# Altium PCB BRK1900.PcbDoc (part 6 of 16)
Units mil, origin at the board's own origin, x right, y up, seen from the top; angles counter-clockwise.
Board outline 8858.27 x 5905.51 mil, 10 copper layers (L1-TOP, L2-GND, L3-PWR, L4-GND, L5-PWR, L6-PWR, L7-GND, L8-SIG, L9-GND, L10-BOT), stack 48.824 mil thick; 456 components, 571 nets, 2296 pads, 2416 vias.
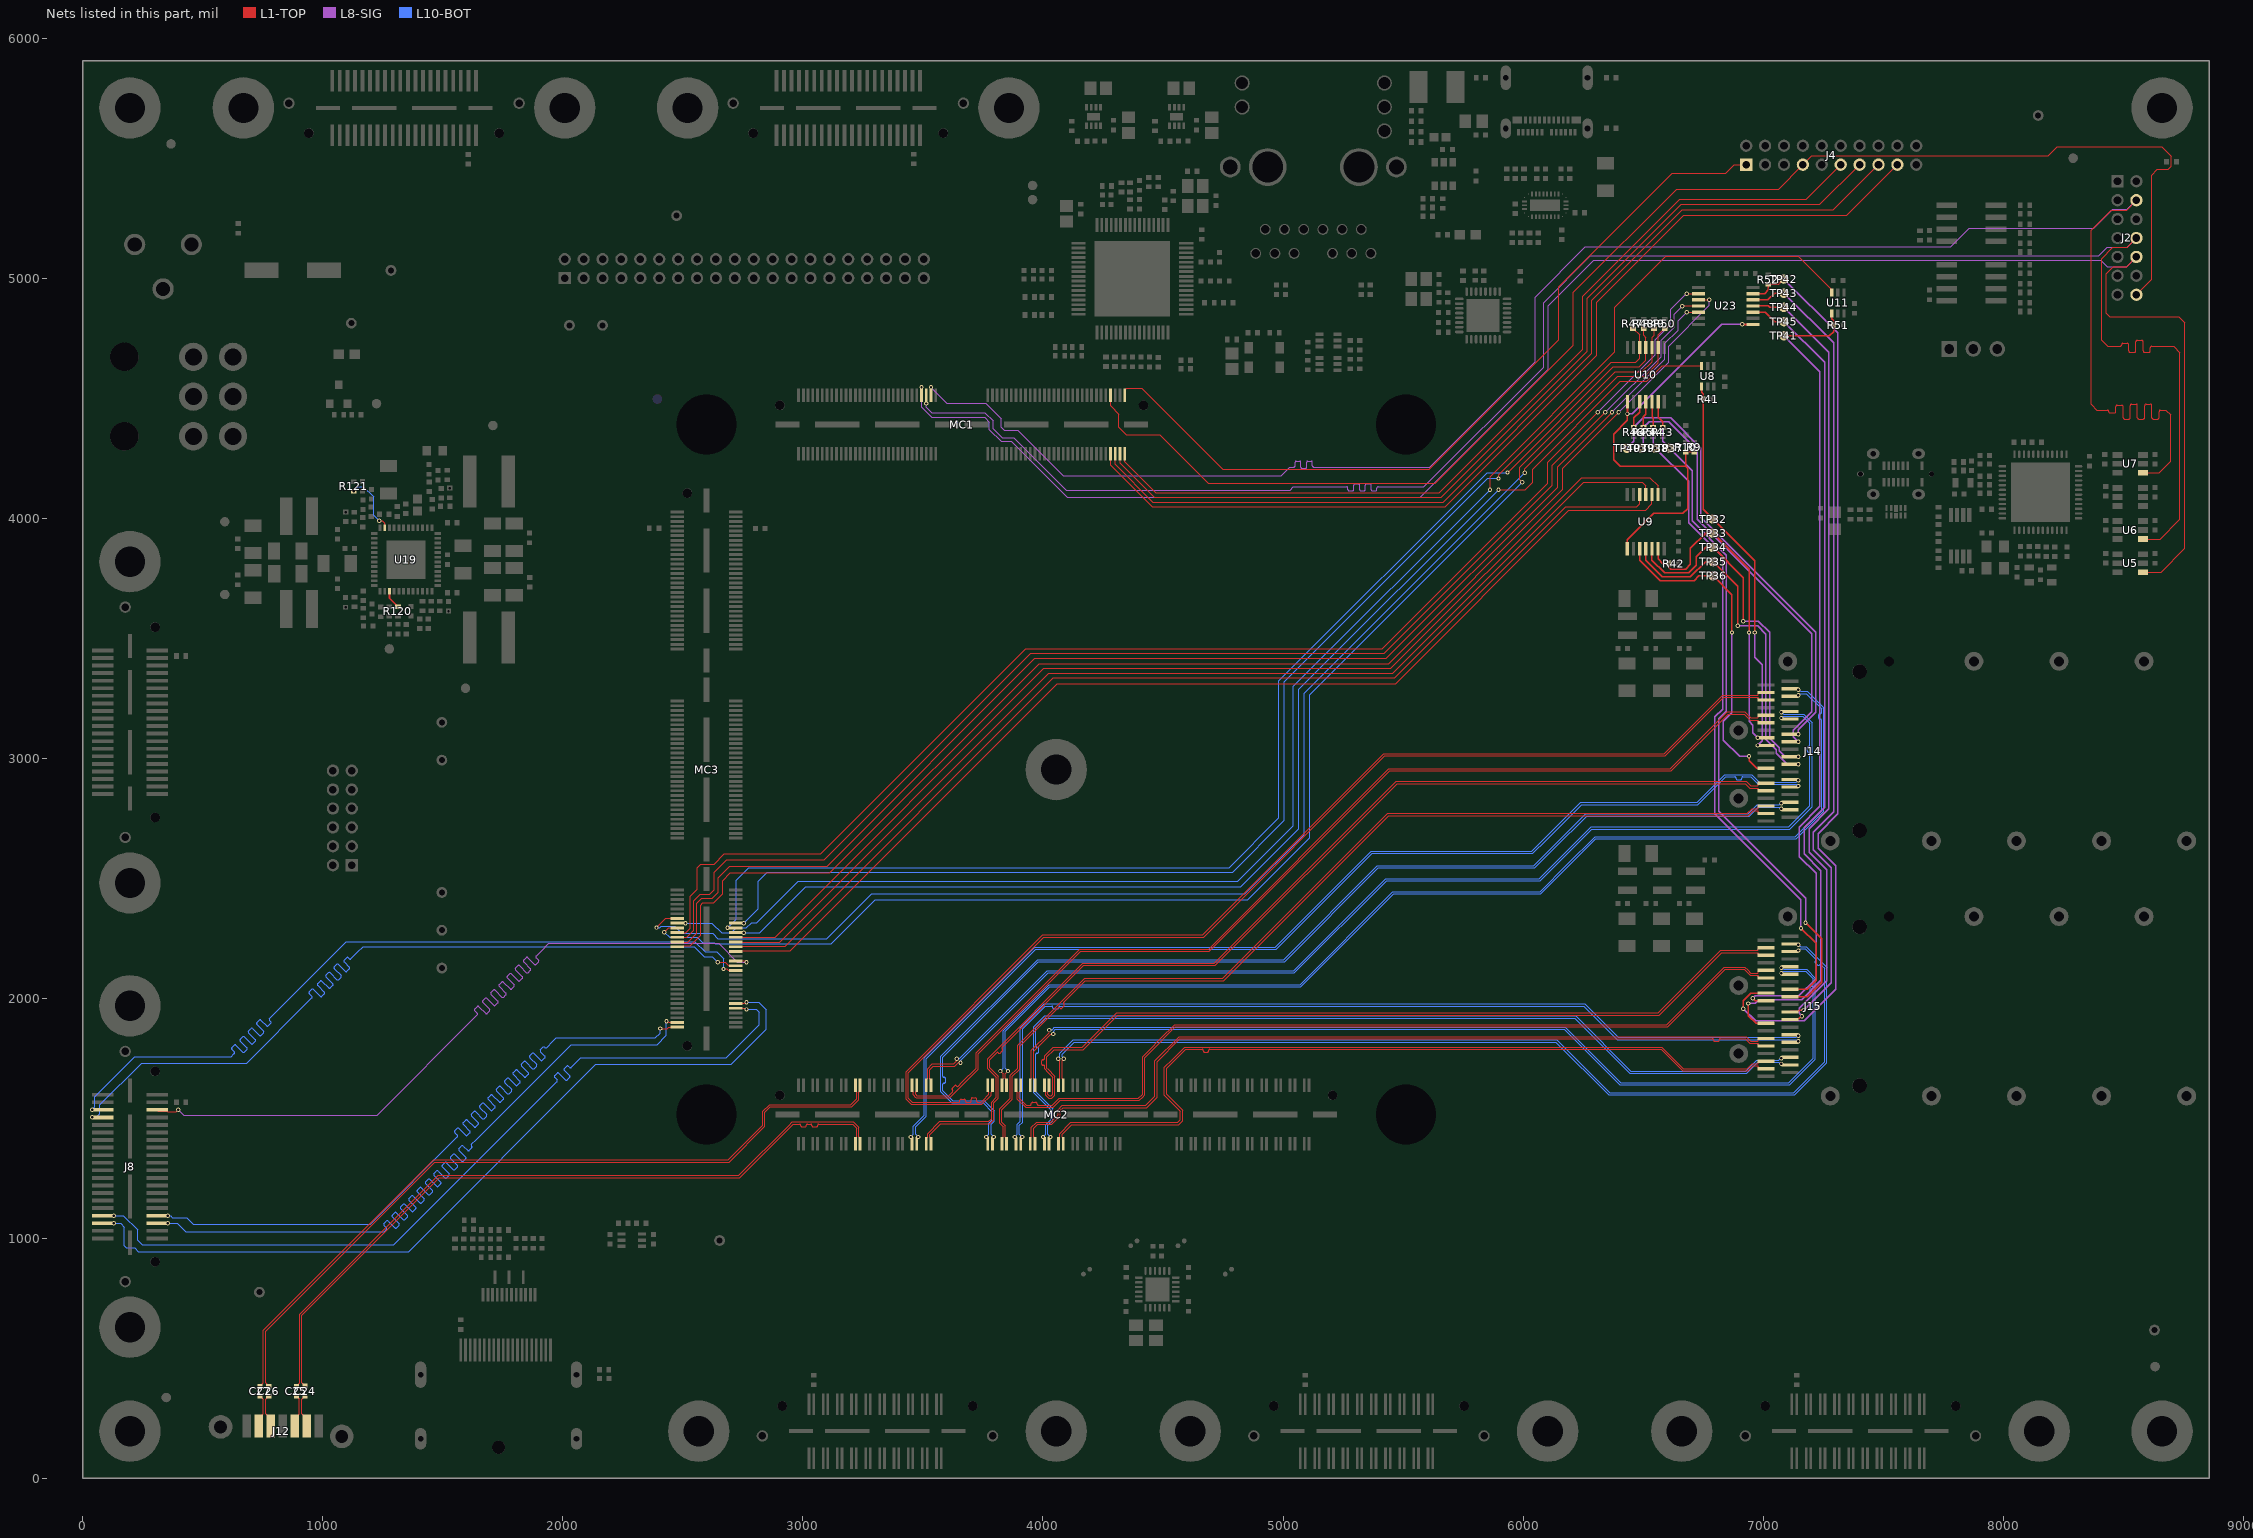
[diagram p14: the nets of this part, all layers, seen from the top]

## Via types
v1: diameter 18, hole 10, L1-TOP to L10-BOT, tented both sides, 2170 vias
v2: diameter 20, hole 10, L1-TOP to L10-BOT, tented both sides, 246 vias

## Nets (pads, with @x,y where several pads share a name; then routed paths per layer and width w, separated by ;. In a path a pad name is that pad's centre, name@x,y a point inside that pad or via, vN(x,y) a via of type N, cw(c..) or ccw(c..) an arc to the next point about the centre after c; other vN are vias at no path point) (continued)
PS_JTAG_TDI: J2.10 MC1.53 U5.4 | length 7725.6
  L1-TOP w4.96: J2.10@8554.76,5088.26 8513.74,5047.24 8458.82,5047.24 8429.13,5017.56 8429.13,4854.33 8444.02,4839.44 8730.86,4839.44 8755.91,4814.4 8755.91,3874.02 8657.1,3775.21 U5.4@8582.3,3775.21
  L8-SIG w4.05: v1(3494.09,4545.42) 3494.09,4462.26 3536.74,4419.62 3756.78,4419.62 3775.96,4400.44 3775.96,4369.22 3825.28,4319.9 3867.73,4319.9 4100.63,4087 5571.48,4087 6104.21,4619.73 6104.21,4884.72 6293.49,5074 8406.31,5074 8432.57,5047.74 8514.24,5047.74 J2.10@8554.76,5088.26
PS_JTAG_TDO: J2.8 MC1.55 U6.4 | length 7834.5
  L1-TOP w4.96: J2.8@8554.76,5167 8515.5,5127.74 8456.07,5127.74 8409.45,5081.12 8409.45,4740.55 8434.51,4715.49 8444.88,4715.49 8486.7,4715.49 ccw(c8486.7,4721.48) 8492.69,4721.48 8492.69,4722.4 cw(c8498.69,4722.4) 8498.69,4728.39 8516.66,4728.39 cw(c8516.66,4722.4) 8522.66,4722.4 8522.66,4696.48 ccw(c8528.65,4696.48) 8528.65,4690.49 8546.63,4690.49 ccw(c8546.63,4696.48) 8552.62,4696.48 8552.62,4734.49 cw(c8558.61,4734.49) 8558.61,4740.49 8576.59,4740.49 cw(c8576.59,4734.49) 8582.58,4734.49 8582.58,4696.48 ccw(c8588.58,4696.48) 8588.58,4690.49 8606.55,4690.49 ccw(c8606.55,4696.48) 8612.55,4696.48 8612.55,4709.49 cw(c8618.54,4709.49) 8618.54,4715.49 8621.02,4715.49 8710.1,4715.49 8736.22,4689.37 8736.22,3996.06 8653.16,3913.01 U6.4@8582.3,3913.01
  L8-SIG w4.05: v1(3513.78,4477.42) 3513.78,4462.93 3537.37,4439.34 3758.43,4439.34 3792.94,4404.82 3792.94,4372.36 3830.33,4334.97 3877.34,4334.97 4096.31,4116 5029.39,4116 5043.31,4129.92 5248.03,4129.92 5265.75,4129.92 cw(c5265.75,4125.11) 5270.56,4125.11 5270.56,4118.81 ccw(c5275.37,4118.81) 5275.37,4114 5289.8,4114 ccw(c5289.8,4118.81) 5294.61,4118.81 5294.61,4138.05 cw(c5299.42,4138.05) 5299.42,4142.86 5313.85,4142.86 cw(c5313.85,4138.05) 5318.66,4138.05 5318.66,4118.81 ccw(c5323.47,4118.81) 5323.47,4114 5337.9,4114 ccw(c5337.9,4118.81) 5342.71,4118.81 5342.71,4138.05 cw(c5347.52,4138.05) 5347.52,4142.86 5361.95,4142.86 cw(c5361.95,4138.05) 5366.76,4138.05 5366.76,4118.81 ccw(c5371.57,4118.81) 5371.57,4114 5386,4114 ccw(c5386,4118.81) 5390.81,4118.81 5390.81,4125.11 cw(c5395.62,4125.11) 5395.62,4129.92 5397.65,4129.92 5586.76,4129.92 6085.9,4629.06 6085.9,4897.58 6280.35,5092.03 8397.15,5092.03 8432.86,5127.74 8515.5,5127.74 J2.8@8554.76,5167
PS_JTAG_TMS: J2.4 MC1.57 U7.4 | length 7910.9
  L1-TOP w4.96: J2.4@8554.76,5324.48 8513.74,5283.46 8450.76,5283.46 8366.14,5198.84 8366.14,4474.52 8390.47,4450.19 8402.51,4450.19 8433.27,4450.19 cw(c8433.27,4444.2) 8439.26,4444.2 ccw(c8445.26,4444.2) 8445.26,4438.21 8463.24,4438.21 ccw(c8463.24,4444.2) 8469.23,4444.2 8469.23,4464.54 cw(c8475.22,4464.54) 8475.22,4470.53 8493.2,4470.53 cw(c8493.2,4464.54) 8499.19,4464.54 8499.19,4418.9 ccw(c8505.18,4418.9) 8505.18,4412.91 8523.16,4412.91 ccw(c8523.16,4418.9) 8529.15,4418.9 8529.15,4469.2 cw(c8535.15,4469.2) 8535.15,4475.19 8553.12,4475.19 cw(c8553.12,4469.2) 8559.12,4469.2 8559.12,4418.9 ccw(c8565.11,4418.9) 8565.11,4412.91 8583.09,4412.91 ccw(c8583.09,4418.9) 8589.08,4418.9 8589.08,4469.2 cw(c8595.07,4469.2) 8595.07,4475.19 8613.05,4475.19 cw(c8613.05,4469.2) 8619.04,4469.2 8619.04,4418.9 ccw(c8625.04,4418.9) 8625.04,4412.91 8643.01,4412.91 ccw(c8643.01,4418.9) 8649.01,4418.9 8649.01,4444.2 cw(c8655,4444.2) 8655,4450.19 8657.48,4450.19 8677.87,4450.19 8696.85,4431.21 8696.85,4236.22 8649.23,4188.6 U7.4@8582.3,4188.6
  L8-SIG w4.05: v1(3533.46,4545.42) 3599.93,4478.95 3761.2,4478.95 3826.77,4413.39 3826.77,4377.95 3839.57,4365.16 3895.34,4365.16 4083.5,4177 4991.96,4177 5027.56,4212.6 5043.31,4212.6 5045.33,4212.6 ccw(c5045.33,4217.41) 5050.14,4217.41 5050.14,4232.79 cw(c5054.95,4232.79) 5054.95,4237.6 5069.38,4237.6 cw(c5069.38,4232.79) 5074.19,4232.79 5074.19,4212.24 ccw(c5079,4212.24) 5079,4207.43 5093.43,4207.43 ccw(c5093.43,4212.24) 5098.24,4212.24 5098.24,4232.79 cw(c5103.05,4232.79) 5103.05,4237.6 5117.48,4237.6 cw(c5117.48,4232.79) 5122.29,4232.79 5122.29,4217.41 ccw(c5127.1,4217.41) 5127.1,4212.6 5173.23,4212.6 5610.49,4212.6 6050.21,4652.32 6050.21,4920.29 6259.52,5129.6 7781.6,5129.6 7859,5207 8377.28,5207 8456.02,5285.74 8516.02,5285.74 J2.4@8554.76,5324.48
PS_MODE0: J4.17 MC1.114 | length 4116.5
  L1-TOP w4.84: MC1.114@4281.5,4268.11 4281.5,4220.5 4454.76,4047.24 5674.95,4047.24 6306.48,4678.77 6306.48,4899.32 6669.16,5262 7348.61,5262 J4.17@7559.06,5472.44
PS_MODE1: J4.15 MC1.116 | length 3999.7
  L1-TOP w4.84: MC1.116@4301.18,4268.11 4301.18,4223.92 4458.17,4066.93 5666.8,4066.93 6286.8,4686.92 6286.8,4907.47 6663.32,5284 7291.87,5284 J4.15@7480.31,5472.44
PS_MODE2: J4.13 MC1.118 | length 3882.5
  L1-TOP w4.84: MC1.118@4320.87,4268.11 4320.87,4228.25 4462.5,4086.61 5658.65,4086.61 6267.11,4695.08 6267.11,4915.63 6658.48,5307 7236.13,5307 J4.13@7401.57,5472.44
PS_MODE3: J4.11 MC1.120 | length 3763.9
  L1-TOP w5: MC1.120@4340.55,4268.11 4340.55,4234.76 4469.02,4106.3 5650.49,4106.3 6247.43,4703.23 6247.43,4923.78 6652.64,5329 7179.39,5329 J4.11@7322.83,5472.44
PS_PROG_B: J4.1 MC1.119 | length 3406.8
  L1-TOP w5: MC1.119@4340.55,4511.42 4340.55,4532.55 4349,4541 4411.76,4541 4748.03,4204.72 5609.72,4204.72 6149,4744 6149,4964.55 6621.45,5437 6844,5437 6879.44,5472.44 J4.1@6929.13,5472.44
PS_SRST_B: J2.14 J4.7 MC1.113 | length 6019.7
  L1-TOP w4.84: MC1.113@4281.5,4511.42 4281.5,4467.22 4314.96,4433.76 4314.96,4377.95 4346.46,4346.46 4487.3,4346.46 4688.09,4145.67 5634.19,4145.67 6208.06,4719.54 6208.06,4940.09 6638.97,5371 7063.91,5371 J4.7@7165.35,5472.44 7202.91,5510 8187.17,5510 8224.41,5547.24 8661.19,5547.24 8700.31,5508.13 8700.31,5464.82 8688.24,5452.76 8641.73,5452.76 8618.11,5429.13 8618.11,4994.13 J2.14@8554.76,4930.78
QSFP1_INT_B: MC3.42 U8.3 | length 5339.4
  L1-TOP w5: v1(5897.64,4118.11) 6007.87,4118.11 6039.37,4149.61 6039.37,4204.72 6405.51,4570.87 6515.75,4570.87 6579.14,4634.26 U8.3@6743.31,4634.26
  L10-BOT w5: v1(2754.08,2273.62) 2820.62,2273.62 3011,2464 4824,2464 5065.96,2705.96 5065.96,3286.43 v1(5897.64,4118.11)
QSFP1_LP_MODE: MC3.36 U9.5 | length 4568.6
  L1-TOP w5: MC3.36@2720.08,2214.57 2722.51,2217 2925.66,2217 4043.31,3334.65 5464.57,3334.65 6177.17,4047.24 6472.44,4047.24 6485.42,4060.22 U9.5@6485.42,4098.98
QSFP1_MODPRS_B: MC3.40 U9.2 | length 4686
  L1-TOP w5: MC3.40@2720.08,2253.94 2883.86,2253.94 4003.94,3374.02 5448.82,3374.02 6244.09,4169.29 6528.38,4169.29 6562.19,4135.48 U9.2@6562.19,4098.98
QSFP1_MODSEL_B: MC3.38 U9.4 | length 4626.2
  L1-TOP w5: MC3.38@2720.08,2234.25 2903.54,2234.25 4023.62,3354.33 5456.69,3354.33 6251.97,4149.61 6496.06,4149.61 6511.01,4134.66 U9.4@6511.01,4098.98
QSFP1_RESET_B: MC3.34 U9.3 | length 4628.2
  L1-TOP w5: MC3.34@2720.08,2194.88 2743.88,2194.88 2748,2199 2947.03,2199 4059.06,3311.02 5468.5,3311.02 6190.89,4033.41 6510.27,4033.41 6536.6,4059.73 U9.3@6536.6,4098.98
QSFP1_RX1N: J14.18 MC2.47 | length 4592.6
  L1-TOP w3.3: MC2.47@3848.43,1637.4 3848.43,1660.5 3843.08,1665.84 3843.08,1685.65 v1(3854.33,1696.9)
  L10-BOT w3.3: v1(3854.33,1696.9) 3843.08,1708.15 3843.08,1861.85 4029.23,2048 5074.62,2048 5461.66,2435.04 6074.08,2435.04 6303.27,2664.23 7138.26,2664.23 7252.11,2778.08 7252.11,3209.52 7183.4,3278.22 7156.18,3278.22 7149.04,3285.37 v1(7146.9,3285.37)
QSFP1_RX1P: J14.17 MC2.45 | length 4592.6
  L1-TOP w3.3: v1(3822.83,1696.9) 3834.08,1685.65 3834.08,1665.02 3828.74,1659.68 MC2.45@3828.74,1637.4
  L10-BOT w3.3: v1(3822.83,1696.9) 3834.08,1708.15 3834.08,1865.58 4025.5,2057 5070.89,2057 5457.93,2444.04 6070.35,2444.04 6185.73,2559.42 6299.54,2673.23 7134.53,2673.23 7243.11,2781.81 7243.11,3156.5 7243.11,3158.15 ccw(c7238.45,3158.15) 7238.45,3162.81 7236.31,3162.81 cw(c7236.31,3167.47) 7231.65,3167.47 7231.65,3181.45 cw(c7236.31,3181.45) 7236.31,3186.11 7238.45,3186.11 ccw(c7238.45,3190.77) 7243.11,3190.77 7243.11,3201.77 7243.11,3205.79 7179.67,3269.22 7156.18,3269.22 7149.04,3262.08 v1(7146.9,3262.08)
QSFP1_RX2N: J14.21 MC2.43 | length 4776.4
  L1-TOP w3.3: MC2.43@3789.37,1637.4 3789.37,1614.17 3784.03,1608.83 3784.03,1596.27 3745.54,1557.79 3632,1557.79 3451.09,1557.79 3430,1578.87 3430,1670 3430,1693.78 4000,2263.78 4665.35,2263.78 5420.06,3018.49 6587.45,3018.49 6831.44,3262.48 6978.24,3262.48 6980.17,3264.41 6980.17,3268.48 6985.41,3273.72 J14.21@7012.61,3273.72
QSFP1_RX2P: J14.22 MC2.41 | length 4776.4
  L1-TOP w3.3: MC2.41@3769.68,1637.4 3769.68,1614.34 3775.03,1609 3775.03,1600 3751.26,1576.23 3741.81,1566.79 3728.64,1566.79 cw(c3728.64,1571.45) 3723.98,1571.45 3723.98,1580.33 ccw(c3719.32,1580.33) 3719.32,1584.99 3705.34,1584.99 ccw(c3705.34,1580.33) 3700.68,1580.33 3700.68,1571.45 cw(c3696.02,1571.45) 3696.02,1566.79 3682.04,1566.79 cw(c3682.04,1571.45) 3677.38,1571.45 3677.38,1574.29 ccw(c3672.72,1574.29) 3672.72,1578.95 3658.74,1578.95 ccw(c3658.74,1574.29) 3654.08,1574.29 3654.08,1571.45 cw(c3649.42,1571.45) 3649.42,1566.79 3638.83,1566.79 3454.82,1566.79 3439,1582.6 3439,1673.73 3439,1690.05 4003.73,2254.78 4669.08,2254.78 5423.79,3009.49 6591.18,3009.49 6835.17,3253.48 6978.24,3253.48 6980.17,3251.54 6980.17,3247.47 6985.41,3242.23 J14.22@7012.61,3242.23
QSFP1_RX3N: J14.15 MC2.39 | length 4701.2
  L1-TOP w3.3: MC2.39@3533.46,1637.4 3533.46,1660.04 3528.12,1665.38 3528.12,1702.33 3543.31,1717.52 3632.87,1717.52 3650.21,1734.85 3653.79,1731.27 v1(3656.53,1731.27)
  L10-BOT w3.3: v1(3656.53,1731.27) 3658.14,1732.89 3658.14,1742.78 4020.99,2105.63 5047.49,2105.63 5431.04,2489.17 6071.14,2489.17 6169.92,2587.95 6286.55,2704.58 7110.03,2704.58 7203.88,2798.44 7203.88,3148.41 7168.56,3183.74 7085.25,3183.74 7078.11,3190.88 v1(7075.97,3190.88)
QSFP1_RX3P: J14.14 MC2.37 | length 4701.2
  L1-TOP w3.3: MC2.37@3513.78,1637.4 3513.78,1660.04 3519.12,1665.38 3519.12,1706.06 3539.58,1726.52 3629.15,1726.52 3643.84,1741.22 3640.26,1744.8 v1(3640.26,1747.53)
  L10-BOT w3.3: v1(3640.26,1747.53) 3641.88,1749.15 3651.78,1749.15 4017.26,2114.63 5043.77,2114.63 5427.31,2498.17 6067.42,2498.17 6157.19,2587.95 6163.56,2594.32 6282.82,2713.58 7106.3,2713.58 7194.88,2802.17 7194.88,3019.4 7194.88,3021.05 ccw(c7190.22,3021.05) 7190.22,3025.71 7188.09,3025.71 cw(c7188.09,3030.37) 7183.43,3030.37 7183.43,3044.35 cw(c7188.09,3044.35) 7188.09,3049.01 7190.22,3049.01 ccw(c7190.22,3053.67) 7194.88,3053.67 7194.88,3074.8 7194.88,3144.69 7188.98,3150.59 7164.83,3174.74 7085.25,3174.74 7078.11,3167.59 v1(7075.97,3167.59)
QSFP1_RX4N: J14.24 MC2.35 | length 4316.4
  L1-TOP w3.3: MC2.35@3474.41,1637.4 3474.41,1614.08 3469.07,1608.74 3469.07,1600.93 3475,1595 3607.8,1595 3616.14,1603.35 3623.66,1610.87 ccw(c3620.37,1614.16) 3623.66,1617.46 3622.15,1618.97 cw(c3625.45,1622.26) 3622.15,1625.56 3632.04,1635.44 cw(c3635.33,1632.15) 3638.63,1635.44 3640.14,1633.93 ccw(c3643.43,1637.23) 3646.73,1633.93 3664.37,1651.57 3721.46,1708.66 3721.46,1772.64 4153.54,2204.72 4689.82,2204.72 5440.94,2955.85 6613.4,2955.85 6850.6,3193.06 6924.07,3193.06 6935.04,3182.09 6949.14,3167.99 6978.24,3167.99 6980.17,3169.92 6980.17,3174 6985.41,3179.24 J14.24@7012.61,3179.24
QSFP1_RX4P: J14.25 MC2.33 | length 4316.4
  L1-TOP w3.3: MC2.33@3454.72,1637.4 3454.72,1614.54 3460.07,1609.19 3460.07,1597.21 3468.64,1588.64 3471.27,1586 3611.52,1586 3730.46,1704.93 3730.46,1768.91 4157.27,2195.72 4693.54,2195.72 5444.67,2946.85 6617.13,2946.85 6854.33,3184.06 6920.34,3184.06 6922.31,3182.09 6928.68,3175.72 6945.41,3158.99 6978.24,3158.99 6980.17,3157.05 6980.17,3152.98 6985.41,3147.74 J14.25@7012.61,3147.74
QSFP1_SCL: MC3.44 R48.1 U10.4 | length 5369.8
  L1-TOP w5: v1(5935,4190) 6374.92,4629.92 6484.25,4629.92 6511.28,4656.95 U10.4@6511.28,4711.19 6511.28,4752.5 6501.97,4761.81 R48.1@6501.97,4789.37
  L10-BOT w5: v1(2686.08,2293.31) 2722,2329.23 2722,2491 2774.76,2543.76 4775.03,2543.76 4982.8,2751.52 4982.8,3322.52 5850.27,4190 v1(5935,4190)
QSFP1_SDA: MC3.46 R47.1 U10.5 | length 5255.8
  L1-TOP w5: v1(5897.64,4165.35) 5897.64,4181.1 6366.14,4649.61 6468.5,4649.61 6485.69,4666.8 U10.5@6485.69,4711.19 6485.69,4763.32 6459.65,4789.37 R47.1@6457.68,4789.37
  L10-BOT w5: v1(2754.08,2312.99) 2814.96,2373.87 2814.96,2488.19 2852.01,2525.24 4789.49,2525.24 5005.8,2741.54 5005.8,3317.97 5853.18,4165.35 v1(5897.64,4165.35)
QSFP1_TX1N: J14.37 MC2.48 | length 3982.4
  L1-TOP w3.3: MC2.48@3848.43,1394.09 3848.43,1416.65 3843.08,1422 3843.08,1468.92 3829,1483 3829,1535.72 3873,1579.72 3873,1675.27 3903,1705.27 3903,1799.72 4045.73,1942.45 4063.38,1960.1 cw(c4066.67,1956.8) 4069.97,1960.1 4071.48,1958.59 ccw(c4074.77,1961.88) 4078.07,1958.59 4087.95,1968.47 ccw(c4084.66,1971.77) 4087.95,1975.06 4086.44,1976.57 cw(c4089.74,1979.87) 4086.44,1983.16 4096.92,1993.64 4176.96,2073.68 4752.45,2073.68 5439.6,2760.83 6937.47,2760.83 6957.68,2781.04 6968.41,2781.04 6978.24,2781.04 6980.17,2779.1 6980.17,2775.03 6985.41,2769.79 J14.37@7012.61,2769.79
QSFP1_TX1P: J14.36 MC2.46 | length 3982.4
  L1-TOP w3.3: MC2.46@3828.74,1394.09 3828.74,1416.63 3834.08,1421.97 3834.08,1465.19 3820,1479.27 3820,1539.45 3864,1583.45 3864,1679 3894,1709 3894,1803.45 4173.23,2082.68 4748.72,2082.68 5435.87,2769.83 6933.74,2769.83 6953.95,2790.04 6972.13,2790.04 6978.24,2790.04 6980.17,2791.97 6980.17,2796.04 6985.41,2801.28 J14.36@7012.61,2801.28
QSFP1_TX2N: J14.2 MC2.44 | length 4450.3
  L10-BOT w3.3: v1(3795.28,1422.09) 3784.03,1433.34 3784.03,1475.03 3793.95,1484.95 3796.59,1487.59 3796.59,1531.73 3755.34,1572.98 3624.07,1572.98 3582.82,1614.23 3582.82,1617.42 3582.82,1642.37 cw(c3587.48,1642.37) 3587.48,1647.03 3589.61,1647.03 ccw(c3589.61,1651.69) 3594.27,1651.69 3594.27,1665.67 ccw(c3589.61,1665.67) 3589.61,1670.33 3587.48,1670.33 cw(c3587.48,1674.99) 3582.82,1674.99 3582.82,1707.68 3582.82,1754.15 3981.11,2152.44 5006.07,2152.44 5396.73,2543.1 5900.55,2543.1 6048.51,2543.1 6131.64,2626.23 6264.13,2758.72 6941.79,2758.72 6979.85,2796.78 7066.69,2796.78 7073.83,2789.64 v1(7075.97,2789.64)
QSFP1_TX2P: J14.3 MC2.42 | length 4450.3
  L10-BOT w3.3: v1(3763.78,1422.09) 3775.03,1433.34 3775.03,1478.76 3787.59,1491.32 3787.59,1528 3751.61,1563.98 3620.35,1563.98 3573.82,1610.5 3573.82,1757.87 3580.18,1764.24 3977.39,2161.44 5002.35,2161.44 5393.01,2552.1 5896.82,2552.1 6044.79,2552.1 6118.92,2626.23 6125.28,2632.59 6260.4,2767.72 6938.06,2767.72 6976.13,2805.78 7066.69,2805.78 7073.83,2812.93 v1(7075.97,2812.93)
QSFP1_TX3N: J14.34 MC2.40 | length 4346.6
  L1-TOP w3.3: MC2.40@3533.46,1394.09 3533.46,1417.18 3528.12,1422.52 3528.12,1432 3574.12,1478 3778.85,1478 3794.72,1493.86 3794.72,1564.12 3814,1583.41 3814,1675 3778,1711 3778,1744.38 3788.96,1755.33 3806.6,1772.98 cw(c3809.89,1769.68) 3813.19,1772.98 3814.7,1771.47 ccw(c3818,1774.76) 3821.29,1771.47 3831.18,1781.35 ccw(c3827.88,1784.65) 3831.18,1787.94 3829.67,1789.45 cw(c3832.96,1792.75) 3829.67,1796.04 3850.96,1817.34 4170.29,2136.67 4718.01,2136.67 5475.88,2894.54 6925.95,2894.54 6944.97,2875.52 6978.24,2875.52 6980.17,2873.59 6980.17,2869.52 6985.41,2864.28 J14.34@7012.61,2864.28
QSFP1_TX3P: J14.33 MC2.38 | length 4346.6
  L1-TOP w3.3: MC2.38@3513.78,1394.09 3513.78,1416.58 3519.12,1421.93 3519.12,1435.73 3570.39,1487 3775.13,1487 3785.72,1497.59 3785.72,1567.85 3805,1587.14 3805,1671.27 3769,1707.27 3769,1748.11 4166.56,2145.67 4714.28,2145.67 5472.15,2903.54 6929.68,2903.54 6948.7,2884.52 6978.24,2884.52 6980.17,2886.46 6980.17,2890.53 6985.41,2895.77 J14.33@7012.61,2895.77
QSFP1_TX4N: J14.5 MC2.36 | length 4499.2
  L10-BOT w3.3: v1(3480.31,1422.09) 3469.07,1433.34 3469.07,1464.07 3511.29,1506.29 3513.92,1508.92 3513.92,1748.17 3969.19,2203.44 4972.07,2203.44 5371.84,2603.2 6040.21,2603.2 6097.44,2660.43 6244.09,2807.09 6728.35,2807.09 6843.36,2922.1 6857.28,2922.1 6882.23,2922.1 cw(c6882.23,2917.44) 6886.89,2917.44 6886.89,2915.31 ccw(c6891.55,2915.31) 6891.55,2910.65 6905.53,2910.65 ccw(c6905.53,2915.31) 6910.19,2915.31 6910.19,2917.44 cw(c6914.85,2917.44) 6914.85,2922.1 6933.07,2922.1 6948.99,2922.1 6979.82,2891.27 7137.61,2891.27 7144.76,2884.13 v1(7146.9,2884.13)
QSFP1_TX4P: J14.6 MC2.34 | length 4499.2
  L10-BOT w3.3: v1(3448.82,1422.09) 3460.07,1433.34 3460.07,1467.79 3504.92,1512.65 3504.92,1751.9 3965.46,2212.44 4968.35,2212.44 5368.11,2612.2 6036.48,2612.2 6084.71,2660.43 6091.08,2666.8 6240.37,2816.09 6724.62,2816.09 6839.63,2931.1 6952.71,2931.1 6983.54,2900.27 7137.61,2900.27 7144.76,2907.42 v1(7146.9,2907.42)
QSFP2_INT_B: MC3.45 U11.3 | length 6508.2
  L1-TOP w5: v1(5862.2,4118.11) 5862.2,4173.23 6381.89,4692.91 6381.89,4877.95 6594.49,5090.55 7145.67,5090.55 7281.04,4955.18 7281.04,4944.37 U11.3@7285.43,4939.98
  L10-BOT w5: v1(2510.77,2312.99) 2620.01,2312.99 2661,2272 2702,2272 2723,2293 2764.64,2293 2787.14,2315.5 2808.5,2315.5 2980.91,2487.91 4811.91,2487.91 5043,2719 5043,3298.91 v1(5862.2,4118.11)
QSFP2_LP_MODE: MC3.37 U23.5 | length 5561.5
  L1-TOP w5: MC3.37@2476.77,2234.25 2520.95,2234.25 2558.65,2271.95 2558.65,2395.65 2579.19,2416.19 2622.18,2416.19 2648.14,2442.15 2648.14,2502.84 2695.3,2550 3101.18,2550 3966.67,3415.49 5430.45,3415.49 6143.57,4128.6 6143.57,4213.56 6370.08,4440.07 v1(6370.08,4440.94) ; v1(6681.1,4858.27) 6681.16,4858.21 U23.5@6730.74,4858.16 U23.5@6730.74,4858.16
  L8-SIG w5: v1(6370.08,4440.94) 6590.55,4661.42 6590.55,4728.35 6645.67,4783.46 6645.67,4822.83 v1(6681.1,4858.27)
QSFP2_MODPRS_B: MC3.41 U23.2 | length 5611.5
  L1-TOP w5: MC3.41@2476.77,2273.62 2512.62,2273.62 2530.31,2291.31 2530.31,2424.77 2560,2454.47 2560,2544 2575,2559 2629.87,2559 2672.87,2602 3074.44,2602 3929.13,3456.69 5413.39,3456.69 6102.36,4145.67 6102.36,4232.28 v1(6311.02,4440.94) ; v1(6681.56,4934.7) 6681.68,4934.82 6730.63,4934.82 U23.2@6730.74,4934.93
  L8-SIG w5: v1(6311.02,4440.94) 6551.18,4681.1 6551.18,4744.09 6614.17,4807.09 6614.17,4870.08 6678.8,4934.7 v1(6681.56,4934.7)
QSFP2_MODSEL_B: MC3.39 U23.4 | length 5578.3
  L1-TOP w5: MC3.39@2476.77,2253.94 2515.94,2253.94 2544.54,2282.54 2544.54,2406.49 2572.04,2434 2612.81,2434 2631.17,2452.36 2631.17,2524.87 2683.3,2577 3088.81,2577 3948.95,3437.14 5421.48,3437.14 6121.91,4137.57 6121.91,4220.34 v1(6342.52,4440.94) ; v1(6662.35,4882.82) 6663.28,4883.75 U23.4@6730.74,4883.75
  L8-SIG w5: v1(6342.52,4440.94) 6574.8,4673.23 6574.8,4740.16 6629.92,4795.28 6629.92,4850.39 v1(6662.35,4882.82)
QSFP2_RESET_B: MC3.35 U23.3 | length 5670.6
  L1-TOP w5: MC3.35@2476.77,2214.57 2500.48,2214.57 2504.92,2219 2530.42,2219 2573.86,2262.44 2573.86,2387.86 2583.42,2397.42 2628.42,2397.42 2666.11,2435.11 2666.11,2489.82 2698.3,2522 3112.55,2522 3984.39,3393.83 5439.42,3393.83 6165.22,4119.63 6165.22,4208.53 v1(6397.64,4440.94) ; U23.3@6730.74,4909.34 6730.8,4909.39 6775.54,4909.39 v1(6775.59,4909.45)
  L8-SIG w5: v1(6397.64,4440.94) 6606.3,4649.61 6606.3,4716.54 6775.59,4885.83 v1(6775.59,4909.45)
QSFP2_RX1N: J15.18 MC2.63 | length 4045.9
  L1-TOP w3.3: MC2.63@4084.65,1637.4 4084.65,1659.97 4079.3,1665.32 4079.3,1739.97 4086.3,1746.97 v1(4086.3,1748.03)
  L10-BOT w3.3: v1(4086.3,1748.03) 4086.3,1750.31 4079.3,1757.31 4079.3,1767.56 4129.51,1817.77 6136.04,1817.77 6356.51,1597.3 7130.7,1597.3 7265,1731.6 7265,2129.09 7249.21,2144.88 7178.87,2215.22 7156.17,2215.22 7149.03,2222.36 v1(7146.89,2222.36)
QSFP2_RX1P: J15.17 MC2.61 | length 4045.9
  L1-TOP w3.3: v1(4063.3,1748.03) 4063.3,1746.97 4070.3,1739.97 4070.3,1665.22 4064.96,1659.88 MC2.61@4064.96,1637.4
  L10-BOT w3.3: v1(4063.3,1748.03) 4063.3,1750.31 4070.3,1757.31 4070.3,1771.29 4125.78,1826.77 6139.76,1826.77 6360.24,1606.3 7126.97,1606.3 7256,1735.33 7256,2125.36 7242.85,2138.52 7241.68,2139.68 ccw(c7238.38,2136.39) 7235.09,2139.68 7233.58,2138.17 cw(c7230.28,2141.47) 7226.99,2138.17 7217.1,2148.06 cw(c7220.4,2151.35) 7217.1,2154.65 7218.61,2156.16 ccw(c7215.32,2159.45) 7218.61,2162.75 7200.52,2180.84 7175.15,2206.22 7156.17,2206.22 7149.03,2199.07 v1(7146.89,2199.07)
QSFP2_RX2N: J15.21 MC2.59 | length 3449.7
  L1-TOP w3.3: MC2.59@4025.59,1637.4 4025.59,1614.69 4020.25,1609.34 4020.25,1599.71 4026.92,1593.04 4033.59,1593.04 4040.8,1600.24 4040.8,1671.8 4019.69,1692.91 4006.75,1705.85 4006.75,1715.04 4006.75,1716.69 ccw(c4002.09,1716.69) 4002.09,1721.35 3999.95,1721.35 cw(c3999.95,1726.01) 3995.29,1726.01 3995.29,1739.99 cw(c3999.95,1739.99) 3999.95,1744.65 4002.09,1744.65 ccw(c4002.09,1749.31) 4006.75,1749.31 4006.75,1759.63 4042.39,1795.28 4164.44,1795.28 4307.92,1938.76 6562.44,1938.76 6823.16,2199.47 6978.23,2199.47 6980.16,2201.4 6980.16,2205.48 6985.4,2210.72 J15.21@7012.61,2210.72
QSFP2_RX2P: J15.22 MC2.57 | length 3449.7
  L1-TOP w3.3: MC2.57@4005.91,1637.4 4005.91,1614.78 4011.25,1609.43 4011.25,1595.98 4023.19,1584.04 4037.32,1584.04 4049.8,1596.51 4049.8,1675.53 4019.69,1705.64 4015.75,1709.58 4015.75,1755.91 4046.12,1786.28 4168.17,1786.28 4311.65,1929.76 6566.17,1929.76 6826.88,2190.47 6978.23,2190.47 6980.16,2188.54 6980.16,2184.46 6985.4,2179.22 J15.22@7012.61,2179.22
QSFP2_RX3N: J15.15 MC2.55 | length 4081.2
  L1-TOP w3.3: MC2.55@3966.54,1637.4 3966.54,1660.04 3961.19,1665.38 3961.19,1780.09 4031.5,1850.39 4041.4,1850.39 v1(4042.35,1851.35)
  L10-BOT w3.3: v1(4042.35,1851.35) 4043.97,1852.96 4043.97,1862.86 4051.18,1870.08 6172.31,1870.08 6402.77,1639.62 7111.01,1639.62 7217.25,1745.86 7217.25,2084.2 7180.72,2120.74 7085.24,2120.74 7078.11,2127.87 v1(7075.96,2127.87)
QSFP2_RX3P: J15.14 MC2.53 | length 4081.2
  L1-TOP w3.3: MC2.53@3946.85,1637.4 3946.85,1660.04 3952.19,1665.38 3952.19,1783.82 4025.13,1856.76 4025.13,1866.66 v1(4026.09,1867.61)
  L10-BOT w3.3: v1(4026.09,1867.61) 4027.7,1869.23 4037.6,1869.23 4042.18,1873.81 4047.45,1879.08 6176.04,1879.08 6406.5,1648.62 7107.28,1648.62 7208.25,1749.59 7208.25,2020.67 7208.25,2022.32 ccw(c7203.59,2022.32) 7203.59,2026.98 7201.46,2026.98 cw(c7201.46,2031.64) 7196.8,2031.64 7196.8,2045.62 cw(c7201.46,2045.62) 7201.46,2050.28 7203.59,2050.28 ccw(c7203.59,2054.94) 7208.25,2054.94 7208.25,2071.85 7208.25,2080.47 7176.99,2111.74 7085.24,2111.74 7078.09,2104.58 v1(7075.96,2104.58)
QSFP2_RX4N: J15.24 MC2.51 | length 3539.9
  L1-TOP w3.3: MC2.51@3907.48,1637.4 3907.48,1614.16 3902.14,1608.82 3902.14,1583.86 3931,1555 3937.99,1555 3947.35,1555 ccw(c3947.35,1559.66) 3952.01,1559.66 3952.01,1561.8 cw(c3956.67,1561.8) 3956.67,1566.46 3970.65,1566.46 cw(c3970.65,1561.8) 3975.31,1561.8 3975.31,1559.66 ccw(c3979.97,1559.66) 3979.97,1555 4004.92,1555 4039.54,1555 4068.34,1583.8 4397.8,1583.8 4415,1601 4415,1756.73 4442.64,1784.36 4491.14,1832.86 4547.97,1889.69 6598.42,1889.69 6609.68,1900.95 6838.78,2130.05 6924.06,2130.05 6935.03,2119.08 6949.13,2104.98 6978.23,2104.98 6980.16,2106.91 6980.16,2110.99 6985.4,2116.23 J15.24@7012.61,2116.23
QSFP2_RX4P: J15.25 MC2.49 | length 3539.9
  L1-TOP w3.3: MC2.49@3887.8,1637.4 3887.8,1614.46 3893.14,1609.11 3893.14,1580.13 3927.27,1546 4004.92,1546 4043.27,1546 4072.07,1574.8 4401.53,1574.8 4417.11,1590.38 4424,1597.27 4424,1753 4449,1778 4551.69,1880.69 6602.15,1880.69 6618.68,1897.22 6842.5,2121.05 6920.34,2121.05 6922.3,2119.08 6928.67,2112.71 6945.4,2095.98 6978.23,2095.98 6980.16,2094.05 6980.16,2089.97 6985.4,2084.73 J15.25@7012.61,2084.73
QSFP2_SCL: MC3.47 R50.1 U10.2 | length 5800
  L1-TOP w4: v1(2390.08,2294.67) 2428.08,2332.68 MC3.47@2476.77,2332.68
  L1-TOP w5: v1(6007,4189) 6007,4205.15 6393.68,4591.83 6507.17,4591.83 6562.46,4647.12 U10.2@6562.46,4711.19 6562.46,4764.24 6587.6,4789.37 R50.1@6589.57,4789.37
  L10-BOT w5: v1(2390.08,2294.67) 2403.67,2294.67 2409,2300 2466,2300 2495,2271 2624,2271 2646,2249 3100,2249 3286,2435 4841,2435 5088,2682 5088,3270 v1(6007,4189)
QSFP2_SDA: MC3.43 R49.1 U10.3 | length 5741.5
  L1-TOP w4: v1(2422.73,2275.73) 2440.31,2293.31 MC3.43@2476.77,2293.31
  L1-TOP w5: v1(5996.06,4149.61) 5986.05,4159.62 5986.05,4212.71 6383.69,4610.35 6494.99,4610.35 6536.87,4652.24 U10.3@6536.87,4711.19 6536.87,4753.41 6545.52,4762.06 R49.1@6545.52,4789.37
  L10-BOT w5: v1(2422.73,2275.73) 2444.47,2254 2559,2254 2582,2231 2630,2231 2634,2227 3119,2227 3302,2410 4853,2410 5111.04,2668.04 5111.04,3264.58 v1(5996.06,4149.61)
QSFP2_TX1N: J15.37 MC2.64 | length 3411.4
  L1-TOP w3.3: MC2.64@4084.65,1394.09 4084.65,1416.73 4079.3,1422.07 4079.3,1433 4120.3,1474 4565.73,1474 4581.54,1489.81 4581.54,1530.27 4581.54,1534 4515,1600.54 4515,1709 4546.57,1740.57 4593.74,1787.74 4637.8,1787.74 4662.75,1787.74 cw(c4662.75,1783.08) 4667.41,1783.08 4667.41,1780.94 ccw(c4672.07,1780.94) 4672.07,1776.28 4686.05,1776.28 ccw(c4686.05,1780.94) 4690.71,1780.94 4690.71,1783.08 cw(c4695.37,1783.08) 4695.37,1787.74 4763.78,1787.74 6574.39,1787.74 6664.31,1697.82 6937.46,1697.82 6957.67,1718.03 6968.4,1718.03 6978.23,1718.03 6980.16,1716.09 6980.16,1712.02 6985.4,1706.78 J15.37@7012.61,1706.78
QSFP2_TX1P: J15.36 MC2.62 | length 3411.4
  L1-TOP w3.3: MC2.62@4064.96,1394.09 4064.96,1417.16 4070.3,1422.5 4070.3,1436.73 4116.58,1483 4562,1483 4572.54,1493.54 4572.54,1530.27 4506,1596.81 4506,1712.73 4540.2,1746.93 4590.01,1796.74 6578.12,1796.74 6668.04,1706.82 6933.73,1706.82 6953.94,1727.03 6972.13,1727.03 ; 6972.13,1727.03 6978.23,1727.03 6980.16,1728.96 6980.16,1733.04 6985.4,1738.28 J15.36@7012.61,1738.28
QSFP2_TX2N: J15.2 MC2.60 | length 3753.2
  L10-BOT w3.3: v1(4031.5,1422.09) 4020.25,1433.34 4020.25,1470.26 4040.81,1490.83 4040.81,1539.83 3970.61,1610.03 3970.61,1742.13 3970.61,1767.08 cw(c3975.27,1767.08) 3975.27,1771.74 3977.41,1771.74 ccw(c3977.41,1776.4) 3982.07,1776.4 3982.07,1790.38 ccw(c3977.41,1790.38) 3977.41,1795.04 3975.27,1795.04 cw(c3975.27,1799.7) 3970.61,1799.7 3970.61,1814.96 3970.61,1876.71 4011.26,1917.35 6215.59,1917.35 6445.09,1687.85 6931.94,1687.85 6977.87,1733.78 7065.18,1733.78 v1@7076.43,1722.53
  other v1: 7075.96,1726.63
QSFP2_TX2P: J15.3 MC2.58 | length 3753.2
  L10-BOT w3.3: v1(4000,1422.09) 4011.25,1433.34 4011.25,1473.99 4031.81,1494.55 4031.81,1536.1 3961.61,1606.3 3961.61,1880.44 4007.53,1926.35 6219.31,1926.35 6448.82,1696.85 6928.22,1696.85 6974.14,1742.78 7065.18,1742.78 v1@7076.43,1754.02
  other v1: 7075.96,1749.92
QSFP2_TX3N: J15.34 MC2.56 | length 3402.2
  L1-TOP w3.3: MC2.56@3966.54,1394.09 3966.54,1417.12 3961.19,1422.46 3961.19,1458.19 3978,1475 4037.06,1475 4072.35,1510.29 4072.35,1532.96 4084.36,1544.97 4431.97,1544.97 4475,1588 4475,1736 4570.54,1831.54 6763.78,1831.54 6788.73,1831.54 cw(c6788.73,1826.88) 6793.39,1826.88 6793.39,1824.74 ccw(c6798.05,1824.74) 6798.05,1820.08 6812.03,1820.08 ccw(c6812.03,1824.74) 6816.69,1824.74 6816.69,1826.88 cw(c6821.35,1826.88) 6821.35,1831.54 6849.41,1831.54 6925.94,1831.54 6944.96,1812.52 6978.23,1812.52 6980.16,1810.58 6980.16,1806.51 6985.4,1801.27 J15.34@7012.61,1801.27
QSFP2_TX3P: J15.33 MC2.54 | length 3402.2
  L1-TOP w3.3: MC2.54@3946.85,1394.09 3946.85,1416.94 3952.19,1422.28 3952.19,1461.92 3974.27,1484 4033.33,1484 4063.35,1514.02 4063.35,1536.69 4080.63,1553.97 4428.24,1553.97 4445,1570.73 4466,1591.73 4466,1739.73 4566.81,1840.54 6763.78,1840.54 6929.67,1840.54 6948.69,1821.52 6978.23,1821.52 6980.16,1823.45 6980.16,1827.52 6985.4,1832.76 J15.33@7012.61,1832.76
QSFP2_TX4N: J15.5 MC2.52 | length 3807.8
  L10-BOT w3.3: v1(3913.39,1422.09) 3902.14,1433.34 3902.14,1471 3915,1483.86 3915,1873.77 4008.61,1967.38 4011.87,1967.38 4036.82,1967.38 cw(c4036.82,1962.72) 4041.48,1962.72 4041.48,1960.58 ccw(c4046.14,1960.58) 4046.14,1955.92 4060.12,1955.92 ccw(c4060.12,1960.58) 4064.78,1960.58 4064.78,1962.72 cw(c4069.44,1962.72) 4069.44,1967.38 4106.3,1967.38 6253.16,1967.38 6392.28,1828.26 7137.61,1828.26 7144.75,1821.12 v1(7146.89,1821.12)
QSFP2_TX4P: J15.6 MC2.50 | length 3807.8
  L10-BOT w3.3: v1(3881.89,1422.09) 3893.14,1433.34 3893.14,1474.73 3906,1487.59 3906,1877.5 4004.88,1976.38 6256.89,1976.38 6396,1837.26 7137.61,1837.26 7144.75,1844.41 v1(7146.89,1844.41)
QSFP_1_INT_B_3V3: J14.28 R41.1 TP32.1 U8.4 | length 1606.9
  L1-TOP w6: U8.4@6743.31,4547.65 6743.31,4524.54 6751,4516.85 R41.1@6751,4495.95 6751,4036.4 TP32.1@6791.34,3996.06 6964.57,3822.83 v1(6964.57,3523.62)
  L8-SIG w6: v1(6964.57,3523.62) 6964.57,3421.26 6996.06,3389.76 6996.06,3072.17 v1(6977.15,3053.25)
QSFP_1_LP_MODE_3V3: J14.31 TP36.1 U9.10 | length 1365.2
  L1-TOP w6: U9.10@6485.42,3872.61 6485.42,3825.61 6570.87,3740.16 6712.6,3740.16 6732.28,3759.84 TP36.1@6791.34,3759.84 6870.08,3681.1 v1(6870.08,3523.62) ; v1(6940.94,3007.87) 6940.94,2990.16 6972.34,2958.76 J14.31@7012.61,2958.76
  L8-SIG w6: v1(6870.08,3523.62) 6870.08,3188.98 6834.65,3153.54 6834.65,3074.8 6901.57,3007.87 v1(6940.94,3007.87)
QSFP_1_MODPRS_B_3V3: J14.27 R42.1 TP33.1 U9.13 | length 1328.7
  L1-TOP w6: U9.13@6562.19,3872.61 6562.19,3831.51 6582.68,3811.02 R42.1@6607.28,3811.02 6607.28,3794.29 6614.17,3787.4 6677.17,3787.4 6696.85,3807.09 6696.85,3874.02 6759.84,3937.01 TP33.1@6791.34,3937.01 6940.94,3787.4 v1(6940.94,3523.62)
  L8-SIG w6: v1(6940.94,3523.62) 6940.94,3153.54 6956.69,3137.8 6956.69,3105.2 v1(6977.15,3084.75)
QSFP_1_MODSEL_B_3V3: J14.8 TP35.1 U9.11 | length 1450.3
  L1-TOP w6: U9.11@6511.01,3872.61 6511.01,3823.64 6578.74,3755.91 6696.85,3755.91 6759.84,3818.9 TP35.1@6791.34,3818.9 6893.7,3716.54 v1(6893.7,3551.18)
  L8-SIG w6: v1(6893.7,3551.18) 6976.38,3551.18 7011.22,3516.33 7011.22,3079.33 7055.12,3035.43 7055.12,3020.57 7101.18,2974.51 v1(7146.9,2974.51)
QSFP_1_RESET_B_3V3: J14.9 TP34.1 U9.12 | length 1476.7
  L1-TOP w6: U9.12@6536.6,3872.61 6536.6,3825.61 6590.55,3771.65 6688.98,3771.65 6720.47,3803.15 6720.47,3838.58 6759.84,3877.95 TP34.1@6791.34,3877.95 6917.32,3751.97 v1(6917.32,3570.87)
  L8-SIG w6: v1(6917.32,3570.87) 6980.27,3570.87 7026.97,3524.16 7026.97,3083.26 7066.93,3043.31 7066.93,3031.85 7092.77,3006.01 v1(7146.9,3006.01)
QSFP_1_SCL_3V3: J14.11 R45.1 TP39.1 U10.11 | length 1937.1
  L1-TOP w6: R45.1@6499.31,4378.05 v1(6501.28,4378.05) 6501.28,4423.36 6511.28,4433.36 U10.11@6511.28,4484.81
  L8-SIG w6: v1(6492.13,4291.34) 6501.28,4300.5 v1(6501.28,4378.05) 6524.81,4401.57 6606.3,4401.57 6724.41,4283.46 6724.41,3996.06 7201.35,3519.12 7201.35,3192.8 7125.98,3117.44 7125.98,3089.91 v1(7146.9,3069)
QSFP_1_SDA_3V3: J14.12 R46.1 TP40.1 U10.10 | length 1981.6
  L1-TOP w6: v1(6461.28,4378.05) 6461.28,4417.36 6485.69,4441.77 U10.10@6485.69,4484.81
  L8-SIG w6: v1(6433.07,4291.34) 6461.28,4319.55 v1(6461.28,4378.05) 6500.56,4417.32 6614.17,4417.32 6740.16,4291.34 6740.16,4003.94 7218.92,3525.18 7218.92,3191.36 7146.9,3119.34 v1(7146.9,3100.5)
QSFP_2_INT_B_3V3: J15.28 R51.1 TP41.1 U11.4 | length 3455
  L1-TOP w6: v1(6956.69,2000) 6966.45,1990.24 J15.28@7012.61,1990.24 ; v1(7086.61,4759.84) 7275.59,4759.84 7293.13,4777.38 R51.1@7293.13,4803.67 7293.13,4823.25 7285.43,4830.94 U11.4@7285.43,4853.36
  L8-SIG w6: v1(6956.69,2000) 6967.14,2010.44 7148.24,2010.44 7220.13,2082.34 7220.13,2520.02 7149.61,2590.55 7149.61,2712.6 7236.22,2799.21 7236.22,4610.24 v1(7086.61,4759.84)
QSFP_2_LP_MODE_3V3: J15.31 TP45.1 U23.10 | length 3504.5
  L1-TOP w6: v1(6938.23,1978.51) 6938.23,1927.69 6970.17,1895.76 J15.31@7012.61,1895.76 ; U23.10@6957.12,4858.16 7007.98,4858.16 7047.24,4818.9 v1(7086.61,4818.9)
  L8-SIG w6: v1(6938.23,1978.51) 6967.64,1978.51 6983.87,1994.74 7160.09,1994.74 7240.16,2074.8 7240.16,2531.5 7170.47,2601.18 7170.47,2709.84 7255.91,2795.28 7255.91,4649.61 v1(7086.61,4818.9)
QSFP_2_MODPRS_B_3V3: J15.27 R52.1 TP42.1 U23.13 | length 3888.6
  L1-TOP w6: v1(6917.32,1956.69) 6917.32,1990.67 6948.4,2021.74 J15.27@7012.61,2021.74 ; U23.13@6957.12,4934.93 7005.79,4934.93 7021.65,4950.79 R52.1@7021.65,4974.41 7062.5,4974.41 7084.15,4996.06 v1(7086.61,4996.06)
  L8-SIG w6: v1(6917.32,1956.69) 6968.33,1905.68 7170.49,1905.68 7303.15,2038.35 7303.15,2551.18 7228.35,2625.98 7228.35,2685.04 7311.02,2767.72 7311.02,4771.65 v1(7086.61,4996.06)
QSFP_2_MODSEL_B_3V3: J15.8 TP44.1 U23.11 | length 3334.3
  L1-TOP w6: U23.11@6957.12,4883.75 7021.76,4883.75 7027.56,4877.95 v1(7086.61,4877.95) ; J15.8@7111.43,1911.5 7115.31,1915.39 7148.47,1915.39 7158.27,1925.2 v1(7161.42,1925.2)
  L8-SIG w6: v1(7086.61,4877.95) 7273.8,4690.76 7273.8,2789.55 7191.2,2706.95 7191.2,2608.01 7263.78,2535.43 7263.78,2073.18 7149.61,1959 7149.61,1937.01 v1(7161.42,1925.2)
QSFP_2_RESET_B_3V3: J15.9 TP43.1 U23.12 | length 3388.5
  L1-TOP w6: U23.12@6957.12,4909.34 7019.57,4909.34 7047.24,4937.01 v1(7086.61,4937.01) ; J15.9@7111.43,1943 7115.31,1946.89 7147.68,1946.89 7150.68,1949.89 v1(7169.39,1949.89)
  L8-SIG w6: v1(7086.61,4937.01) 7293.49,4730.13 7293.49,2777.74 7208.05,2692.3 7208.05,2618.72 7283.46,2543.31 7283.46,2063.96 v1(7169.39,1949.89)
QSFP_2_SCL_3V3: J15.11 R43.1 TP37.1 U10.13 | length 2884.3
  L1-TOP w6: U10.13@6562.46,4484.81 6562.46,4420.18 6581.28,4401.36 v1(6581.28,4378.05) ; J15.11@7111.43,2005.99 7183.16,2005.99 7244.09,2066.93 7244.09,2247.49 v1(7176.42,2315.17)
  L8-SIG w6: v1(6581.28,4378.05) 6581.28,4320.29 v1(6610.24,4291.34) 6704.72,4196.85 6704.72,3988.19 6847.09,3845.82 6847.09,3196.52 6815.57,3164.99 6815.57,2778.49 7176.42,2417.64 v1(7176.42,2315.17)
QSFP_2_SDA_3V3: J15.12 R44.1 TP38.1 U10.12 | length 2843.8
  L1-TOP w6: U10.12@6536.87,4484.81 6536.87,4422.77 6541.28,4418.36 v1(6541.28,4378.05) ; J15.12@7111.43,2037.49 7183.16,2037.49 7220.47,2074.8 7220.47,2228.35 v1(7157.48,2291.34)
  L8-SIG w6: v1(6541.28,4378.05) 6541.28,4301.24 v1(6551.18,4291.34) 6688.98,4153.54 6688.98,3980.31 6830.71,3838.58 6830.71,3204.72 6799.21,3173.23 6799.21,2767.72 7157.48,2409.45 v1(7157.48,2291.34)
QSFP_THREESTATE#: R9.1 R10.2 U9.8 U10.8 U23.8 | length 1869
  L1-TOP w6: U9.8@6434.24,3872.61 6434.24,3910.61 6543.31,4019.68 6665.35,4019.68 6685.04,4039.37 6685.04,4208.66 6677.17,4216.54 ; v1(6434.51,4434.13) 6434.51,4406.95 6377.95,4350.39 6377.95,4244.09 6405.51,4216.54 6677.17,4216.54 ; R9.1@6712.6,4275.59 R10.2@6677.17,4275.59 6677.17,4216.54
  L1-TOP w8: v1(6434.51,4434.13) U10.8@6434.51,4484.81 ; v1(6913.39,4807.09) 6913.44,4807.03 U23.8@6957.12,4806.98 U23.8@6957.12,4806.98
  L8-SIG w6: v1(6434.51,4434.13) 6453.8,4434.13 6826.76,4807.09 v1(6913.39,4807.09)
SATA_RXB+: C27.2 MC2.17 | length 3201.2
  L1-TOP w3.3: C27.2@739.15,384.08 752.65,397.58 752.65,617.38 1462.27,1327 2689,1327 2833,1471 2833,1528.73 2861.27,1557 3199,1557 3223.85,1581.85 3223.85,1609.42 3218.5,1614.76 MC2.17@3218.5,1637.4
SATA_RXB+_C: C27.1 J12.6 | length 139.6
  L1-TOP w3.3: J12.6@732.48,218.5 732.48,248.3 752.98,268.8 752.98,330.09 C27.1@739.15,343.92
SATA_RXB-: C26.2 MC2.19 | length 3201.2
  L1-TOP w3.3: C26.2@775.15,384.08 761.65,397.58 761.65,613.65 1466,1318 2692.73,1318 2842,1467.27 2842,1525 2865,1548 3202.73,1548 3232.85,1578.12 3232.85,1609.42 3238.19,1614.76 MC2.19@3238.19,1637.4
SATA_RXB-_C: C26.1 J12.5 | length 139.4
  L1-TOP w3.3: C26.1@775.15,343.92 761.98,330.75 761.98,268.56 782.48,248.06 J12.5@782.48,218.5
SATA_TXA+: C24.2 MC2.18 | length 3046.4
  L1-TOP w3.3: C24.2@926,384.16 912.5,397.66 912.5,680.5 1485,1253 2736.73,1253 2776.73,1293 2959.73,1476 2961.61,1476 2986.56,1476 cw(c2986.56,1471.34) 2991.22,1471.34 2991.22,1469.3 ccw(c2995.88,1469.3) 2995.88,1464.64 3009.86,1464.64 ccw(c3009.86,1469.3) 3014.52,1469.3 3014.52,1471.34 cw(c3019.18,1471.34) 3019.18,1476 3033.16,1476 cw(c3033.16,1471.34) 3037.82,1471.34 3037.82,1469.3 ccw(c3042.48,1469.3) 3042.48,1464.64 3056.46,1464.64 ccw(c3056.46,1469.3) 3061.12,1469.3 3061.12,1471.34 cw(c3065.78,1471.34) 3065.78,1476 3105.32,1476 3206.84,1476 3223.85,1458.99 3223.85,1421.74 3218.5,1416.4 MC2.18@3218.5,1394.09
SATA_TXA+_C: C24.1 J12.2 | length 139.8
  L1-TOP w3.3: C24.1@926,344 911.98,329.98 911.98,268.74 932.48,248.24 J12.2@932.48,218.5
SATA_TXA-: C25.2 MC2.20 | length 3046.8
  L1-TOP w3.3: C25.2@890,384.08 903.5,397.58 903.5,684.23 1481.27,1262 2733,1262 2941,1470 2956,1485 3205.73,1485 3210.57,1485 3232.85,1462.72 3232.85,1457.88 3232.85,1437.73 3232.85,1422.45 3238.19,1417.11 MC2.20@3238.19,1394.09
SATA_TXA-_C: C25.1 J12.3 | length 139.3
  L1-TOP w3.3: J12.3@882.48,218.5 882.48,247.59 902.98,268.09 902.98,330.94 C25.1@890,343.92
SUPPLY_1_CE: R121.1 U19.23 | length 265.1
  L1-TOP w5: v1@1234.03,3990 v1(1235.03,3989) 1247,3989 1258,3978 U19.23@1258,3959.53
  L10-BOT w5: v1(1129,4112.31) 1148.12,4131.44 1168.92,4131.44 1211.59,4088.77 1211.59,4012.44 v1(1235.03,3989)
SUPPLY_1_RST: R120.1 U19.39 | length 80.4
  L1-TOP w7: U19.39@1277.69,3695.75 1277.69,3666.82 1304.98,3639.52 1304.98,3637.56 1311.32,3631.21 R120.1@1313.29,3631.21
SZG_PORTA_C2P_1: J8.34 MC3.1 | length 3419
  L1-TOP w4.55: v1(2405.51,1874.02) 2434.54,1874.02 2440.45,1879.92 MC3.1@2476.77,1879.92
  L10-BOT w4.55: v1(354.36,1094.51) 366.12,1094.51 374.02,1086.61 433.07,1086.61 460.63,1059.06 1196.85,1059.06 1559.06,1421.26 1560.66,1422.87 ccw(c1557.19,1426.34) 1560.66,1429.81 1549.93,1440.55 cw(c1553.4,1444.02) 1549.93,1447.49 1560.35,1457.91 cw(c1563.82,1454.43) 1567.29,1457.91 1595.7,1429.49 ccw(c1599.17,1432.97) 1602.64,1429.49 1613.06,1439.91 ccw(c1609.59,1443.38) 1613.06,1446.85 1584.65,1475.27 cw(c1588.12,1478.74) 1584.65,1482.21 1595.06,1492.62 cw(c1598.54,1489.15) 1602.01,1492.62 1630.42,1464.21 ccw(c1633.89,1467.69) 1637.36,1464.21 1647.78,1474.63 ccw(c1644.31,1478.1) 1647.78,1481.57 1619.37,1509.98 cw(c1622.84,1513.46) 1619.37,1516.93 1629.78,1527.34 cw(c1633.26,1523.87) 1636.73,1527.34 1665.14,1498.93 ccw(c1668.61,1502.4) 1672.08,1498.93 1682.5,1509.35 ccw(c1679.03,1512.82) 1682.5,1516.29 1654.09,1544.7 cw(c1657.56,1548.18) 1654.09,1551.65 1664.5,1562.06 cw(c1667.97,1558.59) 1671.45,1562.06 1699.86,1533.65 ccw(c1703.33,1537.12) 1706.8,1533.65 1717.22,1544.07 ccw(c1713.75,1547.54) 1717.22,1551.01 1688.81,1579.42 cw(c1692.28,1582.89) 1688.81,1586.37 1699.22,1596.78 cw(c1702.69,1593.31) 1706.17,1596.78 1734.58,1568.37 ccw(c1738.05,1571.84) 1741.52,1568.37 1751.94,1578.79 ccw(c1748.46,1582.26) 1751.94,1585.73 1723.52,1614.14 cw(c1727,1617.61) 1723.52,1621.08 1733.94,1631.5 cw(c1737.41,1628.03) 1740.88,1631.5 1769.3,1603.09 ccw(c1772.77,1606.56) 1776.24,1603.09 1786.66,1613.5 ccw(c1783.18,1616.98) 1786.66,1620.45 1758.24,1648.86 cw(c1761.72,1652.33) 1758.24,1655.8 1768.66,1666.22 cw(c1772.13,1662.75) 1775.6,1666.22 1804.01,1637.81 ccw(c1807.49,1641.28) 1810.96,1637.81 1821.37,1648.22 ccw(c1817.9,1651.7) 1821.37,1655.17 1792.96,1683.58 cw(c1796.43,1687.05) 1792.96,1690.52 1803.38,1700.94 cw(c1806.85,1697.47) 1810.32,1700.94 1838.73,1672.53 ccw(c1842.21,1676) 1845.68,1672.53 1856.09,1682.94 ccw(c1852.62,1686.41) 1856.09,1689.89 1827.68,1718.3 cw(c1831.15,1721.77) 1827.68,1725.24 1838.1,1735.66 cw(c1841.57,1732.19) 1845.04,1735.66 1873.45,1707.25 ccw(c1876.92,1710.72) 1880.4,1707.25 1890.81,1717.66 ccw(c1887.34,1721.13) 1890.81,1724.61 1862.4,1753.02 cw(c1865.87,1756.49) 1862.4,1759.96 1872.82,1770.38 cw(c1876.29,1766.9) 1879.76,1770.38 1908.17,1741.96 ccw(c1911.64,1745.44) 1915.12,1741.97 1925.53,1752.38 ccw(c1922.06,1755.85) 1925.53,1759.32 1906.64,1778.22 cw(c1910.11,1781.69) 1906.64,1785.16 1917.05,1795.58 cw(c1920.52,1792.11) 1924,1795.58 1925.21,1794.36 ccw(c1928.68,1797.83) 1932.16,1794.36 1960.63,1822.83 1972.44,1834.65 2385.83,1834.65 2405.51,1854.33 v1(2405.51,1874.02)
SZG_PORTA_C2P_2: J8.36 MC3.3 | length 3419.7
  L1-TOP w4.55: v1(2431.77,1904.54) 2435.41,1904.54 2440.35,1899.61 MC3.3@2476.77,1899.61
  L10-BOT w4.55: v1(354.36,1063.01) 393.68,1063.01 428.26,1028.43 1256.78,1028.43 1263.78,1035.43 1265.39,1037.04 ccw(c1261.92,1040.51) 1265.39,1043.99 1254.65,1054.72 cw(c1258.13,1058.19) 1254.65,1061.66 1265.07,1072.08 cw(c1268.54,1068.61) 1272.01,1072.08 1300.43,1043.67 ccw(c1303.9,1047.14) 1307.37,1043.67 1317.78,1054.08 ccw(c1314.31,1057.56) 1317.79,1061.03 1289.37,1089.44 cw(c1292.85,1092.91) 1289.37,1096.38 1299.79,1106.8 cw(c1303.26,1103.33) 1306.73,1106.8 1335.14,1078.39 ccw(c1338.62,1081.86) 1342.09,1078.39 1352.5,1088.8 ccw(c1349.03,1092.27) 1352.5,1095.75 1324.09,1124.16 cw(c1327.56,1127.63) 1324.09,1131.1 1334.51,1141.52 cw(c1337.98,1138.05) 1341.45,1141.52 ; 1341.45,1141.52 1369.86,1113.11 ccw(c1373.34,1116.58) 1376.81,1113.11 1387.22,1123.52 ccw(c1383.75,1126.99) 1387.22,1130.47 1358.81,1158.88 cw(c1362.28,1162.35) 1358.81,1165.82 1369.23,1176.24 cw(c1372.7,1172.76) 1376.17,1176.24 1404.58,1147.82 ccw(c1408.05,1151.3) 1411.53,1147.82 1421.94,1158.24 ccw(c1418.47,1161.71) 1421.94,1165.18 1393.53,1193.6 cw(c1397,1197.07) 1393.53,1200.54 1403.95,1210.95 cw(c1407.42,1207.48) 1410.89,1210.95 1439.3,1182.54 ccw(c1442.77,1186.02) 1446.25,1182.54 1456.66,1192.96 ccw(c1453.19,1196.43) 1456.66,1199.9 1428.25,1228.31 cw(c1431.72,1231.79) 1428.25,1235.26 1438.66,1245.67 cw(c1442.14,1242.2) 1445.61,1245.67 1474.02,1217.26 ccw(c1477.49,1220.73) 1480.96,1217.26 1491.38,1227.68 ccw(c1487.91,1231.15) 1491.38,1234.62 1462.97,1263.03 cw(c1466.44,1266.51) 1462.97,1269.98 1473.38,1280.39 cw(c1476.86,1276.92) 1480.33,1280.39 1508.74,1251.98 ccw(c1512.21,1255.45) 1515.68,1251.98 1526.1,1262.4 ccw(c1522.63,1265.87) 1526.1,1269.34 1497.69,1297.75 cw(c1501.16,1301.22) 1497.69,1304.7 1508.1,1315.11 cw(c1511.57,1311.64) 1515.05,1315.11 1543.46,1286.7 ccw(c1546.93,1290.17) 1550.4,1286.7 1560.82,1297.12 ccw(c1557.35,1300.59) 1560.82,1304.06 1532.41,1332.47 cw(c1535.88,1335.94) 1532.41,1339.41 1542.82,1349.83 cw(c1546.29,1346.36) 1549.77,1349.83 1578.18,1321.42 ccw(c1581.65,1324.89) 1585.12,1321.42 1595.54,1331.83 ccw(c1592.06,1335.31) 1595.54,1338.78 1567.13,1367.19 cw(c1570.6,1370.66) 1567.13,1374.13 1577.54,1384.55 cw(c1581.01,1381.08) 1584.48,1384.55 1602.92,1366.12 ccw(c1606.39,1369.59) 1609.86,1366.12 1620.28,1376.53 ccw(c1616.8,1380) 1620.28,1383.48 1619.52,1384.23 cw(c1622.99,1387.7) 1619.52,1391.18 1641.73,1413.39 2035.43,1807.09 2393.7,1807.09 2431.77,1845.16 v1(2431.77,1904.54)
SZG_PORTA_P2C_1: J8.33 MC3.10 | length 3419.7
  L1-TOP w4.55: MC3.10@2720.08,1958.66 2756.4,1958.66 2761.44,1953.62 v1(2765.08,1953.62)
  L10-BOT w4.55: v1(128.76,1094.51) 169.27,1094.51 228.35,1035.43 228.35,992.13 248.03,972.44 1295.28,972.44 1974.41,1651.57 1976.02,1653.18 ccw(c1972.55,1656.66) 1976.02,1660.13 1965.28,1670.86 cw(c1968.76,1674.33) 1965.28,1677.81 1975.7,1688.22 cw(c1979.17,1684.75) 1982.64,1688.22 2011.06,1659.81 ccw(c2014.53,1663.28) 2018,1659.81 2028.41,1670.23 ccw(c2024.94,1673.7) 2028.41,1677.17 2005.94,1699.65 cw(c2009.41,1703.12) 2005.94,1706.59 2016.35,1717.01 cw(c2019.82,1713.54) 2023.3,1717.01 2028.1,1712.21 ccw(c2031.57,1715.68) 2035.04,1712.21 2070.87,1748.03 2074.8,1751.97 2681.1,1751.97 2818.9,1889.76 2818.9,1940.94 2806.22,1953.62 v1(2765.08,1953.62)
SZG_PORTA_P2C_2: J8.35 MC3.12 | length 3419.7
  L1-TOP w4.55: MC3.12@2720.08,1978.35 2756.5,1978.35 2761.44,1983.28 v1(2765.08,1983.28)
  L10-BOT w4.55: v1(128.76,1063.01) 157.46,1063.01 173.23,1047.24 173.23,968.5 181.1,960.63 216.54,960.63 232.28,944.88 1358.27,944.88 2137.8,1724.41 2700.79,1724.41 2846.46,1870.08 2846.46,1952.76 2815.93,1983.28 v1(2765.08,1983.28)
SZG_PORTA_S0: J8.5 MC3.26 | length 3419
  L1-TOP w4.55: v1(2669.29,2122.05) 2682.44,2122.05 2688.34,2116.14 MC3.26@2720.08,2116.14
  L10-BOT w4.55: v1(39.35,1535.52) 51.18,1547.36 51.18,1590.25 217.23,1756.3 275.4,1756.3 618.51,1756.3 630.18,1767.98 631.79,1769.58 ccw(c628.32,1773.06) 631.79,1776.53 621.06,1787.26 cw(c624.53,1790.73) 621.06,1794.21 631.47,1804.62 cw(c634.94,1801.15) 638.41,1804.62 666.83,1776.21 ccw(c670.3,1779.68) 673.77,1776.21 684.19,1786.63 ccw(c680.71,1790.1) 684.19,1793.57 655.77,1821.98 cw(c659.25,1825.45) 655.77,1828.92 666.19,1839.34 cw(c669.66,1835.87) 673.13,1839.34 701.55,1810.93 ccw(c705.02,1814.4) 708.49,1810.93 718.9,1821.34 ccw(c715.43,1824.82) 718.9,1828.29 690.49,1856.7 cw(c693.96,1860.17) 690.49,1863.64 700.91,1874.06 cw(c704.38,1870.59) 707.85,1874.06 736.26,1845.65 ccw(c739.74,1849.12) 743.21,1845.65 753.62,1856.06 ccw(c750.15,1859.54) 753.62,1863.01 725.21,1891.42 cw(c728.68,1894.89) 725.21,1898.36 735.63,1908.78 cw(c739.1,1905.31) 742.57,1908.78 766.03,1885.32 ccw(c769.5,1888.79) 772.97,1885.32 783.39,1895.74 ccw(c779.92,1899.21) 783.39,1902.68 777.61,1908.46 cw(c781.08,1911.93) 777.61,1915.4 820.87,1958.66 1098.42,2236.22 2550.08,2236.22 2593.39,2192.91 2641.35,2192.91 2669.29,2164.97 v1(2669.29,2122.05)
SZG_PORTA_S1: J8.6 MC3.30 | length 3483.8
  L1-TOP w4.55: J8.6@309.65,1535.51 315.38,1529.79 352.13,1529.79 355,1526.91 389.63,1526.91 v1(398.23,1535.51) ; MC3.30@2720.08,2155.51 2756.4,2155.51 2761.44,2150.48 v1(2765.08,2150.48)
  L8-SIG w4.05: v1(398.23,1535.51) 420.43,1513.31 1225.91,1513.31 1641.99,1929.39 1643.43,1930.83 ccw(c1640.02,1934.23) 1643.43,1937.63 1632.55,1948.5 cw(c1635.95,1951.91) 1632.55,1955.31 1642.75,1965.51 cw(c1646.15,1962.11) 1649.56,1965.51 1678.11,1936.96 ccw(c1681.51,1940.36) 1684.91,1936.96 1695.11,1947.16 ccw(c1691.71,1950.56) 1695.12,1953.96 1666.56,1982.52 cw(c1669.96,1985.92) 1666.56,1989.32 1676.77,1999.52 cw(c1680.17,1996.12) 1683.57,1999.52 1712.12,1970.97 ccw(c1715.52,1974.37) 1718.92,1970.97 1729.13,1981.17 ccw(c1725.73,1984.57) 1729.13,1987.98 1700.57,2016.53 cw(c1703.98,2019.93) 1700.57,2023.33 1710.78,2033.53 cw(c1714.18,2030.13) 1717.58,2033.53 1746.13,2004.98 ccw(c1749.53,2008.38) 1752.94,2004.98 1763.14,2015.18 ccw(c1759.74,2018.59) 1763.14,2021.99 1734.59,2050.54 cw(c1737.99,2053.94) 1734.59,2057.34 1744.79,2067.55 cw(c1748.19,2064.15) 1751.59,2067.55 1780.14,2038.99 ccw(c1783.55,2042.39) 1786.95,2038.99 1797.15,2049.2 ccw(c1793.75,2052.6) 1797.15,2056 1768.6,2084.55 cw(c1772,2087.95) 1768.6,2091.35 1778.8,2101.56 cw(c1782.2,2098.16) 1785.6,2101.56 1814.16,2073 ccw(c1817.56,2076.41) 1820.96,2073.01 1831.16,2083.21 ccw(c1827.76,2086.61) 1831.16,2090.01 1802.61,2118.56 cw(c1806.01,2121.97) 1802.61,2125.37 1812.81,2135.57 cw(c1816.21,2132.17) 1819.62,2135.57 1848.17,2107.02 ccw(c1851.57,2110.42) 1854.97,2107.02 1865.17,2117.22 ccw(c1861.77,2120.62) 1865.17,2124.02 1836.62,2152.58 cw(c1840.02,2155.98) 1836.62,2159.38 1846.82,2169.58 cw(c1850.23,2166.18) 1853.63,2169.58 1881.64,2141.57 ccw(c1885.04,2144.97) 1888.44,2141.57 1898.64,2151.78 ccw(c1895.24,2155.18) 1898.64,2158.58 1888.31,2168.91 cw(c1891.71,2172.31) 1888.31,2175.71 1911.42,2198.82 1940.94,2228.35 2649.61,2228.35 2727.48,2150.48 v1(2765.08,2150.48)
SZG_PORTA_S2: J8.7 MC3.28 | length 3419
  L1-TOP w4.55: v1(2645.67,2149.61) 2677.17,2149.61 2690.94,2135.83 MC3.28@2720.08,2135.83
  L10-BOT w4.55: v1(39.35,1504) 56.33,1504.01 70.87,1518.55 70.87,1555.91 244.95,1729.99 682.75,1729.99 952.76,2000 954.36,2001.61 ccw(c950.89,2005.08) 954.36,2008.55 943.63,2019.29 cw(c947.1,2022.76) 943.63,2026.23 954.05,2036.65 cw(c957.52,2033.17) 960.99,2036.65 989.4,2008.23 ccw(c992.87,2011.71) 996.35,2008.23 1006.76,2018.65 ccw(c1003.29,2022.12) 1006.76,2025.59 978.35,2054.01 cw(c981.82,2057.48) 978.35,2060.95 988.77,2071.37 cw(c992.24,2067.89) 995.71,2071.37 1024.12,2042.95 ccw(c1027.59,2046.43) 1031.06,2042.95 1041.48,2053.37 ccw(c1038.01,2056.84) 1041.48,2060.31 1013.07,2088.72 cw(c1016.54,2092.2) 1013.07,2095.67 1023.48,2106.08 cw(c1026.96,2102.61) 1030.43,2106.08 1058.84,2077.67 ccw(c1062.31,2081.14) 1065.78,2077.67 1076.2,2088.09 ccw(c1072.73,2091.56) 1076.2,2095.03 1047.79,2123.44 cw(c1051.26,2126.92) 1047.79,2130.39 1058.2,2140.8 cw(c1061.68,2137.33) 1065.15,2140.8 1093.56,2112.39 ccw(c1097.03,2115.86) 1100.5,2112.39 1110.92,2122.81 ccw(c1107.45,2126.28) 1110.92,2129.75 1089.15,2151.52 cw(c1092.63,2154.99) 1089.15,2158.46 1099.57,2168.87 cw(c1103.04,2165.4) 1106.51,2168.87 1110.6,2164.79 ccw(c1114.07,2168.26) 1117.54,2164.79 1145.67,2192.91 1167.85,2215.09 2547.23,2215.09 2589.09,2173.23 2622.05,2173.23 v1(2645.67,2149.61)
